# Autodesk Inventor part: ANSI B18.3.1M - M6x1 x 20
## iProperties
Comments: To add or edit properties for Autodesk Inventor files, use iProperties.
Created: 2003-07
Part Number: ANSI B18.3.1M - M6x1 x 20
Vendor: Autodesk Inc.
Document SubType Name: Modeling
Designer: Administrator
Material: Default
Description: Forged Socket Head Cap Screw x Metric
Standard: ANSI B18.3.1M
Manufacturer: Standard
Standards Organization: Custom
Density: 1 g/cm^3
Alert: To add or edit properties for Autodesk Inventor files, use iProperties.
Control State: 0
Master: False
Checked Out: False
Shininess: 64.0
Length Units: 11269
Angle Units: 11279
Time Units: 11290
Mass Units: 11283
Length Display Precision: 3
Angle Display Precision: 2
Compacted: True
EGR: 1
Classification: un/spsc 31161501
Density: 0.0
Volumn: 0.0
Area: 0.0
PropertySet Name: Model Information
Author: Administrator
Revision Number: 5
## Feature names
1. Body [Revolution]
2. Slot [Extrusion]
3. Fillet1
4. Chamfer1
